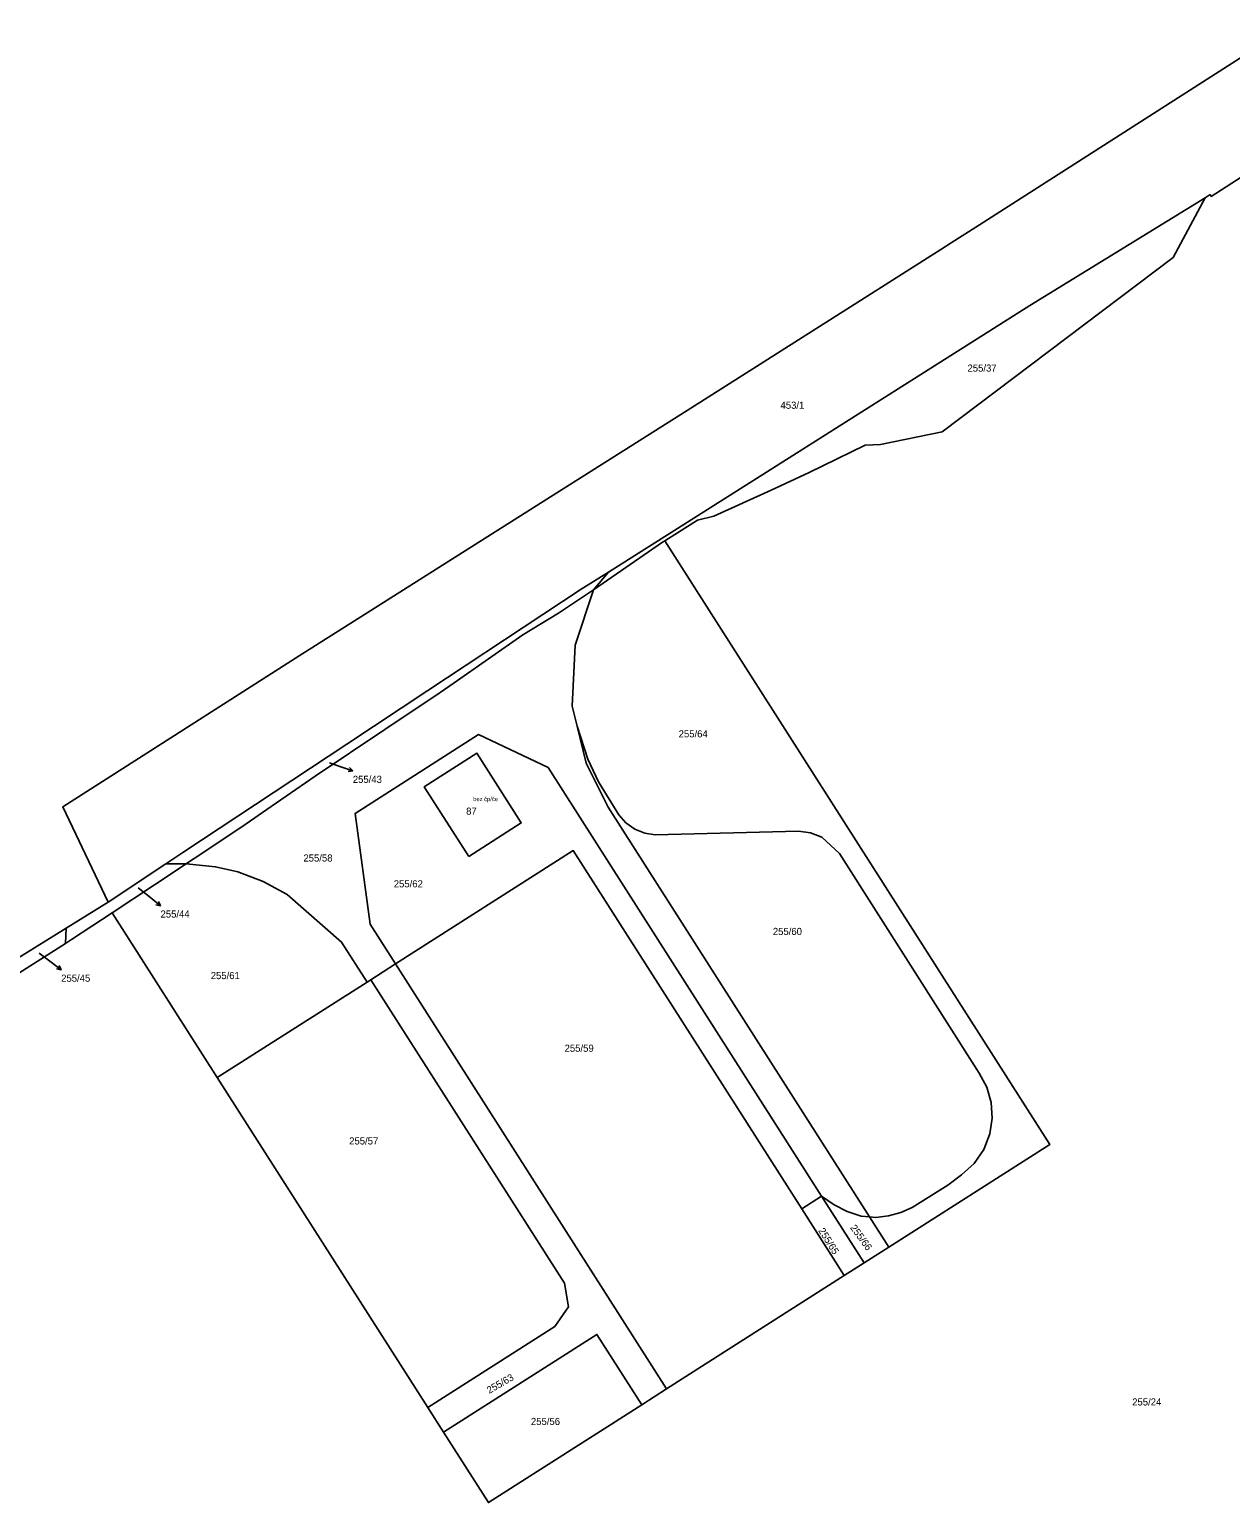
# Model space of a CAD drawing. Extents: x -882150 to -879379, y -1022570 to -1019819.
# Drawn here: x -881331.4 to -881044.6, y -1021727.8 to -1021376 of the extents above; entities that cross this region are included whole.
import ezdxf

# ---------------------------------------------------------------- set-up
doc = ezdxf.new("R2010")
doc.units = 0
for name, color, linetype in [('Definiční body', 7, 'Continuous'), ('Hranice parcel', 7, 'Continuous'), ('Parcelní čísla', 7, 'Continuous'), ('Polygon budovy', 7, 'Continuous'), ('Pop  PČ popisy', 7, 'Continuous')]:
    doc.layers.add(name, color=color, linetype=linetype)

msp = doc.modelspace()

# ---------------------------------------------------------------- linework, layer by layer
at = {"layer": 'Hranice parcel'}
for p, q in [((-881104.49, -1021422.63), (-881111.33, -1021426.97)), ((-881111.33, -1021426.97), (-881113.77, -1021428.52)), ((-881193.13, -1021505.58), (-881196.69, -1021509.86)), ((-881294.79, -1021572.58), (-881298.89, -1021575.3)), ((-881298.89, -1021575.3), (-881312.63, -1021584.39)), ((-881298.89, -1021575.3), (-881294, -1021575.27)), ((-881322.62, -1021590.62), (-881312.63, -1021584.39)), ((-881286.57, -1021626.3), (-881311.66, -1021586.96)), ((-881322.62, -1021590.62), (-881322.84, -1021594.27)), ((-881249.92, -1021602.94), (-881244.02, -1021599.18)), ((-881244.02, -1021599.18), (-881179.26, -1021700.7)), ((-881250.81, -1021603.51), (-881286.57, -1021626.3)), ((-881249.92, -1021602.94), (-881250.81, -1021603.51)), ((-881236.3, -1021705.14), (-881286.57, -1021626.3)), ((-881146.99, -1021657.69), (-881142.26, -1021654.66)), ((-881132.09, -1021670.61), (-881142.26, -1021654.66)), ((-881136.83, -1021673.64), (-881146.99, -1021657.69)), ((-881130.81, -1021659.61), (-881126.19, -1021666.85)), ((-881126.19, -1021666.85), (-881132.09, -1021670.61)), ((-881132.09, -1021670.61), (-881136.83, -1021673.64)), ((-881136.83, -1021673.64), (-881179.26, -1021700.7)), ((-881179.26, -1021700.7), (-881185.16, -1021704.46)), ((-881232.53, -1021711.03), (-881236.3, -1021705.14))]:
    msp.add_line(p, q, dxfattribs=at)
for points in [[(-880699.29, -1021162.79), (-880808.35, -1021233.5), (-880873.35, -1021274.78), (-880941.52, -1021318.31), (-881007.7, -1021360.64), (-881104.49, -1021422.63)], [(-881002.75, -1021385.97), (-881049.18, -1021415.84), (-881049.46, -1021415.4), (-881050.64, -1021416.17)], [(-881050.64, -1021416.17), (-881092.51, -1021441.93), (-881193.13, -1021505.58)], [(-881050.64, -1021416.17), (-881058.28, -1021430.46), (-881113.44, -1021472.06), (-881128.18, -1021475.11), (-881131.8, -1021475.29), (-881145.19, -1021481.79), (-881154.25, -1021486.02), (-881167.98, -1021492.26), (-881171.91, -1021493.15), (-881179.7, -1021498.09)], [(-881113.77, -1021428.52), (-881173.49, -1021466.42), (-881207.85, -1021488.16), (-881267.04, -1021525.56), (-881323.49, -1021561.63), (-881312.63, -1021584.39)], [(-881179.7, -1021498.09), (-881180.26, -1021498.45), (-881196.69, -1021509.86)], [(-881179.7, -1021498.09), (-881087.72, -1021642.3), (-881126.19, -1021666.85)], [(-881193.13, -1021505.58), (-881199.64, -1021509.7), (-881236.31, -1021533.89), (-881255.66, -1021546.66), (-881294.79, -1021572.58)], [(-881196.69, -1021509.86), (-881205.07, -1021515.37), (-881213.6, -1021520.57), (-881229.96, -1021532.07), (-881233.32, -1021534.32), (-881233.59, -1021534.5), (-881246.59, -1021543.22), (-881263.22, -1021554.32), (-881274.72, -1021562.26), (-881279.69, -1021565.69), (-881291.01, -1021573.26), (-881292.96, -1021574.57), (-881294, -1021575.27)], [(-881200.62, -1021542.39), (-881201.8, -1021537.65), (-881201.12, -1021523.07), (-881196.69, -1021509.86)], [(-881244.02, -1021599.18), (-881250.06, -1021589.71), (-881253.66, -1021563.22), (-881224.15, -1021544.4), (-881207.55, -1021552.3), (-881142.26, -1021654.66)], [(-881130.81, -1021659.61), (-881193.25, -1021561.71), (-881198.44, -1021551.19), (-881200.62, -1021542.39)], [(-881130.81, -1021659.61), (-881129.25, -1021659.78), (-881126.25, -1021659.36), (-881123.34, -1021658.54), (-881120.57, -1021657.32), (-881112.06, -1021652.01), (-881108.79, -1021649.56), (-881105.77, -1021646.81), (-881103.49, -1021643.5), (-881102.03, -1021639.76), (-881101.49, -1021636.01), (-881101.75, -1021632.24), (-881102.79, -1021628.6), (-881104.58, -1021625.27), (-881137.97, -1021572.81), (-881142.22, -1021568.94), (-881144.91, -1021567.87), (-881147.77, -1021567.46), (-881181.95, -1021568.36), (-881184.48, -1021567.96), (-881186.87, -1021566.98), (-881188.97, -1021565.49), (-881190.68, -1021563.56), (-881195.52, -1021555.7), (-881198.05, -1021550.25), (-881200.62, -1021542.39)], [(-881226.52, -1021573.5), (-881213.96, -1021565.48), (-881224.57, -1021548.87), (-881237.13, -1021556.89), (-881226.52, -1021573.5)], [(-881146.99, -1021657.69), (-881201.57, -1021572.1), (-881244.02, -1021599.18)], [(-881294, -1021575.27), (-881301.56, -1021580.32), (-881311.66, -1021586.96)], [(-881294, -1021575.27), (-881286.99, -1021575.95), (-881281.64, -1021577.18), (-881275.57, -1021579.48), (-881269.85, -1021582.57), (-881256.9, -1021593.95), (-881250.81, -1021603.51)], [(-881311.66, -1021586.96), (-881321.38, -1021593.34), (-881322.84, -1021594.27)], [(-881338.3, -1021600.38), (-881334.17, -1021597.83), (-881322.62, -1021590.62)], [(-881322.84, -1021594.27), (-881333.12, -1021600.8), (-881333.75, -1021601.2)], [(-881236.3, -1021705.14), (-881205.97, -1021685.79), (-881202.68, -1021681.09), (-881203.68, -1021675.43), (-881249.92, -1021602.94)], [(-881142.26, -1021654.66), (-881139.26, -1021656.7), (-881136.14, -1021658.35), (-881132.77, -1021659.39), (-881130.81, -1021659.61)], [(-881185.16, -1021704.46), (-881195.88, -1021687.66), (-881232.53, -1021711.03)], [(-881185.16, -1021704.46), (-881221.81, -1021727.83), (-881232.53, -1021711.03)]]:
    msp.add_lwpolyline(points, dxfattribs=at)
at = {"layer": 'Polygon budovy'}
msp.add_lwpolyline([(-881226.52, -1021573.5), (-881213.96, -1021565.48), (-881224.57, -1021548.87), (-881237.13, -1021556.89)], close=True, dxfattribs=at)
at = {"layer": 'Pop  PČ popisy'}
for p, q in [((-881259.74, -1021551.15), (-881257.03, -1021552.1)), ((-881257.03, -1021552.1), (-881254.193, -1021553.077)), ((-881254.193, -1021553.077), (-881255.302, -1021553.224)), ((-881254.193, -1021553.077), (-881254.976, -1021552.278)), ((-881305.5, -1021580.98), (-881302.47, -1021583.39)), ((-881302.47, -1021583.39), (-881300.138, -1021585.279)), ((-881300.138, -1021585.279), (-881301.231, -1021585.037)), ((-881300.138, -1021585.279), (-881300.601, -1021584.259)), ((-881329.1, -1021596.58), (-881326.23, -1021598.77)), ((-881326.23, -1021598.77), (-881323.833, -1021600.576)), ((-881323.833, -1021600.576), (-881324.934, -1021600.373)), ((-881323.833, -1021600.576), (-881324.332, -1021599.573))]:
    msp.add_line(p, q, dxfattribs=at)

# ---------------------------------------------------------------- texts
at = {"layer": 'Definiční body'}
msp.add_text('bez čp/če', height=1, dxfattribs=at).set_placement((-881225.44, -1021560.3))
at = {"layer": 'Parcelní čísla'}
for s, p in [('255/37', (-881107.39, -1021457.71)), ('453/1', (-881152.05, -1021466.58)), ('255/64', (-881176.38, -1021545.07)), ('255/43', (-881254.2, -1021555.938)), ('87', (-881227.131, -1021563.54)), ('255/58', (-881266, -1021574.73)), ('255/62', (-881244.421, -1021580.9)), ('255/44', (-881300.12, -1021588.108)), ('255/60', (-881153.88, -1021592.27)), ('255/61', (-881288.137, -1021602.81)), ('255/45', (-881323.85, -1021603.438)), ('255/59', (-881203.62, -1021620.16)), ('255/57', (-881255.07, -1021642.31)), ('255/24', (-881068.06, -1021704.65)), ('255/56', (-881211.66, -1021709.31))]:
    msp.add_text(s, height=1.7, dxfattribs=at).set_placement(p)
for s, rotation, p in [('255/65', 302, (-881143.093, -1021662.881)), ('255/66', 306, (-881135.509, -1021662.202)), ('255/63', 30, (-881221.6, -1021701.899))]:
    msp.add_text(s, height=1.7, rotation=rotation, dxfattribs=at).set_placement(p)

doc.saveas('drawing.dxf')
